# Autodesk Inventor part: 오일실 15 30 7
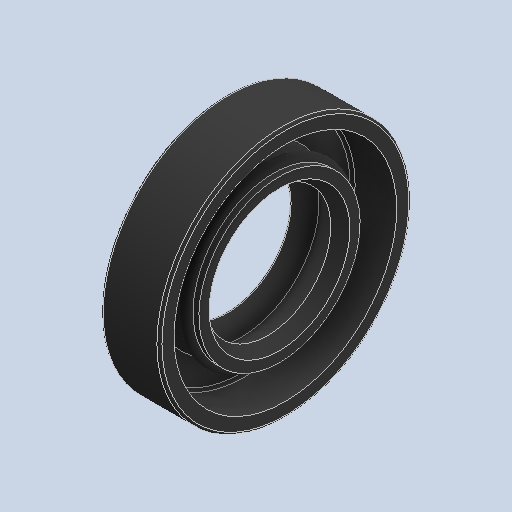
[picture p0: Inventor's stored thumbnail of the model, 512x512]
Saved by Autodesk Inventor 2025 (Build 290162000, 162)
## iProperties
Created: 2024-07
Part Number: 오일실 15 30 7
Material: 고무
Description: 오일-실
Document SubType Name: Modeling
Designer: onair
Density: 0.93 g/cm^3
Appearance: 기본값
Author: jhkim
Sending System: Autodesk Inventor 2025
Preprocessor: ST-DEVELOPER v20
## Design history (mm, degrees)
feature "Solid1"
node "솔리드1"
